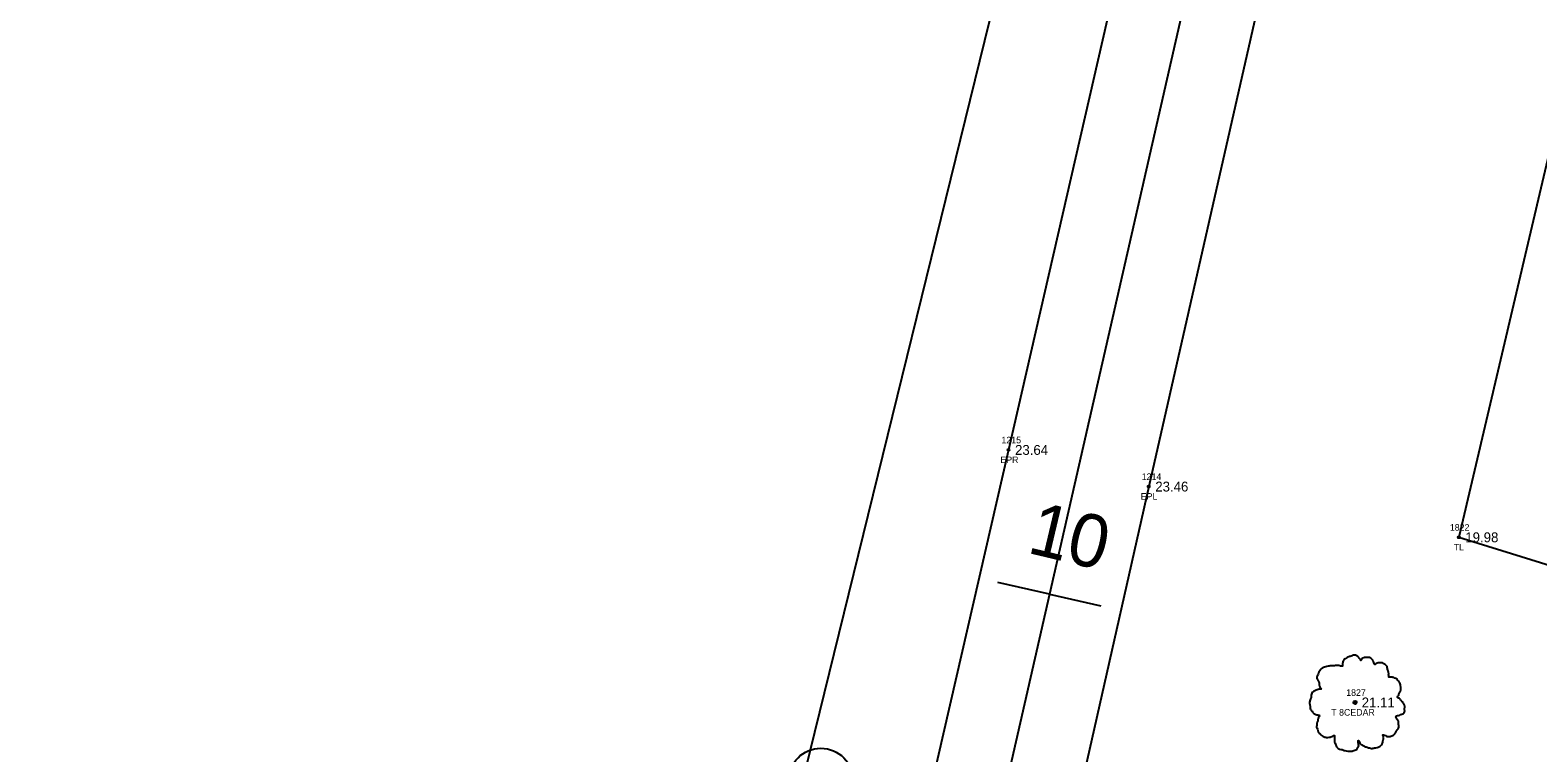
# Model space of a CAD drawing. Extents: x 2654414 to 2656963, y 761776 to 764965.
# Drawn here: x 2655478.7 to 2655707.7, y 762860.3 to 762969.9 of the extents above; entities that cross this region are included whole.
import ezdxf

# ---------------------------------------------------------------- set-up
doc = ezdxf.new("R2010")
doc.units = 0
for name, color, linetype in [('Default', 7, 'Continuous'), ('RD_EX_Road', 7, 'Continuous'), ('RD_EX_Road_txCode', 7, 'Continuous'), ('RD_EX_TX_Road_ELEV', 7, 'Continuous'), ('RD_EX_TX_VEG_ELEV', 7, 'Continuous'), ('RD_EX_UT', 7, 'Continuous'), ('RD_EX_VEG', 7, 'Continuous'), ('RD_EX_VEG_txCode', 7, 'Continuous'), ('RD_HC_Cl', 7, 'Continuous'), ('RD_HC_Data_Tic', 7, 'Continuous'), ('RD_HC_TX_Sta50', 7, 'Continuous'), ('RD_SMD_Locator', 7, 'Continuous')]:
    doc.layers.add(name, color=color, linetype=linetype)

msp = doc.modelspace()

# ---------------------------------------------------------------- linework, layer by layer
at = {"layer": 'Default'}
msp.add_line((2656050.51, 764712.37), (2655383.26, 761787.51), dxfattribs=at)
at = {"layer": 'RD_EX_Road'}
for points in [[(2655700.99, 763232.28), (2655693.55, 763198.57), (2655671.65, 763102.04), (2655649.04, 763001.06), (2655627.27, 762906.23), (2655605, 762809.37), (2655598.99, 762783.09), (2655583.65, 762714.14), (2655561.97, 762618.32), (2655556.36, 762593.84), (2655548.11, 762557.14), (2655540.1, 762522.48), (2655518.03, 762425.04), (2655496.48, 762329.56), (2655475.55, 762236.62), (2655473.2, 762226.14), (2655466.57, 762197.5), (2655460.06, 762168.16), (2655454.26, 762143.78), (2655432.5, 762049.88), (2655410.7, 761955.51), (2655388.17, 761858.43), (2655373.5, 761793.95)], [(2655670.04, 762995.18), (2655648.57, 762900.67), (2655631.27, 762824.03), (2655626.67, 762802.87), (2655621.78, 762781.91), (2655611.71, 762738.43), (2655604.93, 762708.62), (2655582.64, 762610.54), (2655576.46, 762583.32), (2655561.41, 762517.24), (2655539.15, 762414.81), (2655531.98, 762386.15), (2655517.98, 762324.29), (2655508.17, 762280.15), (2655501.46, 762251.6), (2655496.92, 762232.09), (2655477.2, 762144.97), (2655472.14, 762122.52), (2655453.74, 762045.1), (2655431.79, 761949.92), (2655409.76, 761853.25), (2655401.25, 761816.42), (2655394.61, 761787.37)]]:
    msp.add_lwpolyline(points, dxfattribs=at)
at = {"layer": 'RD_EX_UT'}
msp.add_circle((2655598.78, 762856.05), 4.91, dxfattribs=at)
at = {"layer": 'RD_EX_VEG'}
for points in [[(2655677.34, 763211.22), (2655657.55, 763106.21), (2655584.57, 762809.42), (2655537.65, 762768.62), (2655489.1, 762755.63)], [(2655759.38, 763179.69), (2655740.4, 763083.12), (2655695.66, 762892.97), (2655758.37, 762873.59)]]:
    msp.add_lwpolyline(points, dxfattribs=at)
for centre, radius in [((2655679.92, 762867.91), 0.25), ((2655679.91, 762867.89), 0.0001)]:
    msp.add_circle(centre, radius, dxfattribs=at)
for points in [[(2655680.05, 762875.08), (2655679.75, 762875.1), (2655679.43, 762875), (2655679.18, 762874.9), (2655678.95, 762874.83), (2655678.73, 762874.73), (2655678.43, 762874.55), (2655678.2, 762874.35), (2655678.08, 762874.1), (2655678.03, 762873.88), (2655677.98, 762873.6), (2655677.98, 762873.43), (2655677.85, 762873.4), (2655677.7, 762873.43), (2655677.45, 762873.5), (2655677.2, 762873.5), (2655676.95, 762873.5), (2655676.6, 762873.48), (2655676.25, 762873.48), (2655675.98, 762873.43), (2655675.65, 762873.38), (2655675.28, 762873.25), (2655674.93, 762873.13), (2655674.63, 762872.88), (2655674.38, 762872.4), (2655674.25, 762872.05), (2655674.1, 762871.8), (2655674.25, 762871.35), (2655674.43, 762871), (2655674.45, 762870.8), (2655674.53, 762870.38), (2655674.63, 762870.15), (2655674.75, 762869.95), (2655674.68, 762869.93), (2655674.3, 762869.88), (2655674, 762869.78), (2655673.58, 762869.55), (2655673.35, 762869.33), (2655673.25, 762869), (2655673.23, 762868.65), (2655673.13, 762868.45), (2655673.05, 762868.18), (2655673.03, 762868.1), (2655672.98, 762867.78), (2655673.08, 762867.33), (2655673.1, 762866.98), (2655673.23, 762866.75), (2655673.38, 762866.58), (2655673.55, 762866.33), (2655673.95, 762866.11), (2655674.28, 762866.01), (2655674.48, 762865.98), (2655674.3, 762865.48), (2655674.25, 762865.13), (2655674.13, 762864.73), (2655674.13, 762864.66), (2655674.08, 762864.18), (2655674.23, 762863.86), (2655674.3, 762863.48), (2655674.48, 762863.26), (2655674.75, 762862.96), (2655675.08, 762862.73), (2655675.58, 762862.61), (2655675.98, 762862.63), (2655676.55, 762862.81), (2655676.8, 762862.88), (2655676.78, 762862.71), (2655676.8, 762862.33), (2655676.8, 762861.91), (2655676.95, 762861.58), (2655677.05, 762861.31), (2655677.2, 762861.06), (2655677.53, 762860.83), (2655677.93, 762860.76), (2655678.35, 762860.61), (2655678.8, 762860.53), (2655679.3, 762860.51), (2655679.9, 762860.66), (2655680.17, 762860.78), (2655680.27, 762860.96), (2655680.47, 762861.33), (2655680.42, 762861.56), (2655680.45, 762862.16), (2655680.55, 762861.98), (2655680.72, 762861.63), (2655681.22, 762861.33), (2655681.62, 762861.16), (2655682.1, 762861.01), (2655682.4, 762860.93), (2655682.87, 762861.01), (2655683.25, 762861.08), (2655683.62, 762861.21), (2655683.92, 762861.48), (2655684.1, 762861.76), (2655684.15, 762862.03), (2655684.22, 762862.41), (2655684.27, 762862.58)], [(2655684.27, 762862.58), (2655684.2, 762862.76), (2655684.15, 762863.01), (2655684.22, 762862.98), (2655684.4, 762862.93), (2655684.67, 762862.81), (2655684.9, 762862.73), (2655685.22, 762862.76), (2655685.5, 762862.86), (2655685.95, 762863.13), (2655686.22, 762863.61), (2655686.5, 762864.01), (2655686.57, 762864.33), (2655686.52, 762864.56), (2655686.5, 762865.06), (2655686.3, 762865.31), (2655686.25, 762865.43), (2655686.15, 762865.83), (2655686.22, 762865.88), (2655686.5, 762865.93), (2655686.87, 762866.06), (2655687.15, 762866.18), (2655687.37, 762866.36), (2655687.45, 762866.58), (2655687.42, 762866.98), (2655687.47, 762867.38), (2655687.4, 762867.53), (2655687.3, 762867.68), (2655687.22, 762867.88), (2655687.07, 762868.03), (2655686.97, 762868.18), (2655686.87, 762868.28), (2655686.75, 762868.43), (2655686.57, 762868.55), (2655686.42, 762868.6), (2655686.37, 762868.75), (2655686.52, 762868.95), (2655686.57, 762869.05), (2655686.6, 762869.28), (2655686.82, 762869.63), (2655686.87, 762870.03), (2655686.82, 762870.45), (2655686.77, 762870.73), (2655686.62, 762871), (2655686.42, 762871.25), (2655686.3, 762871.43), (2655686.12, 762871.55), (2655685.8, 762871.68), (2655685.55, 762871.73), (2655685.2, 762871.73), (2655685, 762871.78), (2655685.02, 762871.83), (2655685.02, 762871.98), (2655685.02, 762872.25), (2655684.95, 762872.7), (2655684.8, 762873.2), (2655684.8, 762873.23), (2655684.7, 762873.48), (2655684.47, 762873.68), (2655684.3, 762873.78), (2655684.1, 762873.9), (2655683.85, 762873.93), (2655683.55, 762873.93), (2655683.27, 762873.88), (2655683.07, 762873.78), (2655682.9, 762873.65), (2655682.82, 762873.8), (2655682.72, 762874.1), (2655682.67, 762874.25), (2655682.52, 762874.43), (2655682.3, 762874.63), (2655681.85, 762874.75), (2655681.22, 762874.68), (2655680.92, 762874.48), (2655680.77, 762874.3), (2655680.72, 762874.43), (2655680.52, 762874.63), (2655680.42, 762874.8), (2655680.25, 762874.93), (2655680.1, 762875.03), (2655680, 762875.08)]]:
    msp.add_spline(points, degree=3, dxfattribs=at)
at = {"layer": 'RD_HC_Cl'}
msp.add_line((2656050.51, 764712.37), (2655383.26, 761787.51), dxfattribs=at)
at = {"layer": 'RD_HC_Data_Tic'}
for q in [(2655625.68, 762886.11), (2655641.28, 762882.55)]:
    msp.add_line((2655633.48, 762884.33), q, dxfattribs=at)
at = {"layer": 'RD_SMD_Locator'}
for centre in [(2655627.27, 762906.23), (2655648.57, 762900.67), (2655695.66, 762892.97), (2655679.92, 762867.91)]:
    msp.add_circle(centre, 0.15, dxfattribs=at)

# ---------------------------------------------------------------- texts
at = {"layer": 'RD_EX_Road_txCode'}
for s, p in [('1215', (2655626.21, 762907.23)), ('EPR', (2655626.04, 762904.23)), ('1214', (2655647.51, 762901.67)), ('EPL', (2655647.36, 762898.67))]:
    msp.add_text(s, height=1, dxfattribs=at).set_placement(p)
at = {"layer": 'RD_EX_TX_Road_ELEV'}
for s, p in [('23.64', (2655628.27, 762905.48)), ('23.46', (2655649.57, 762899.92))]:
    msp.add_text(s, height=1.5, dxfattribs=at).set_placement(p)
at = {"layer": 'RD_EX_TX_VEG_ELEV'}
for s, p in [('19.98', (2655696.66, 762892.22)), ('21.11', (2655680.92, 762867.16))]:
    msp.add_text(s, height=1.5, dxfattribs=at).set_placement(p)
at = {"layer": 'RD_EX_VEG_txCode'}
for s, p in [('1822', (2655694.31, 762893.97)), ('TL', (2655694.89, 762890.97)), ('1827', (2655678.57, 762868.91)), ('T 8CEDAR', (2655676.3, 762865.91))]:
    msp.add_text(s, height=1, dxfattribs=at).set_placement(p)
at = {"layer": 'RD_HC_TX_Sta50'}
msp.add_text('10', height=8, rotation=346.6686, dxfattribs=at).set_placement((2655629.91, 762890.67))

doc.saveas('drawing.dxf')
